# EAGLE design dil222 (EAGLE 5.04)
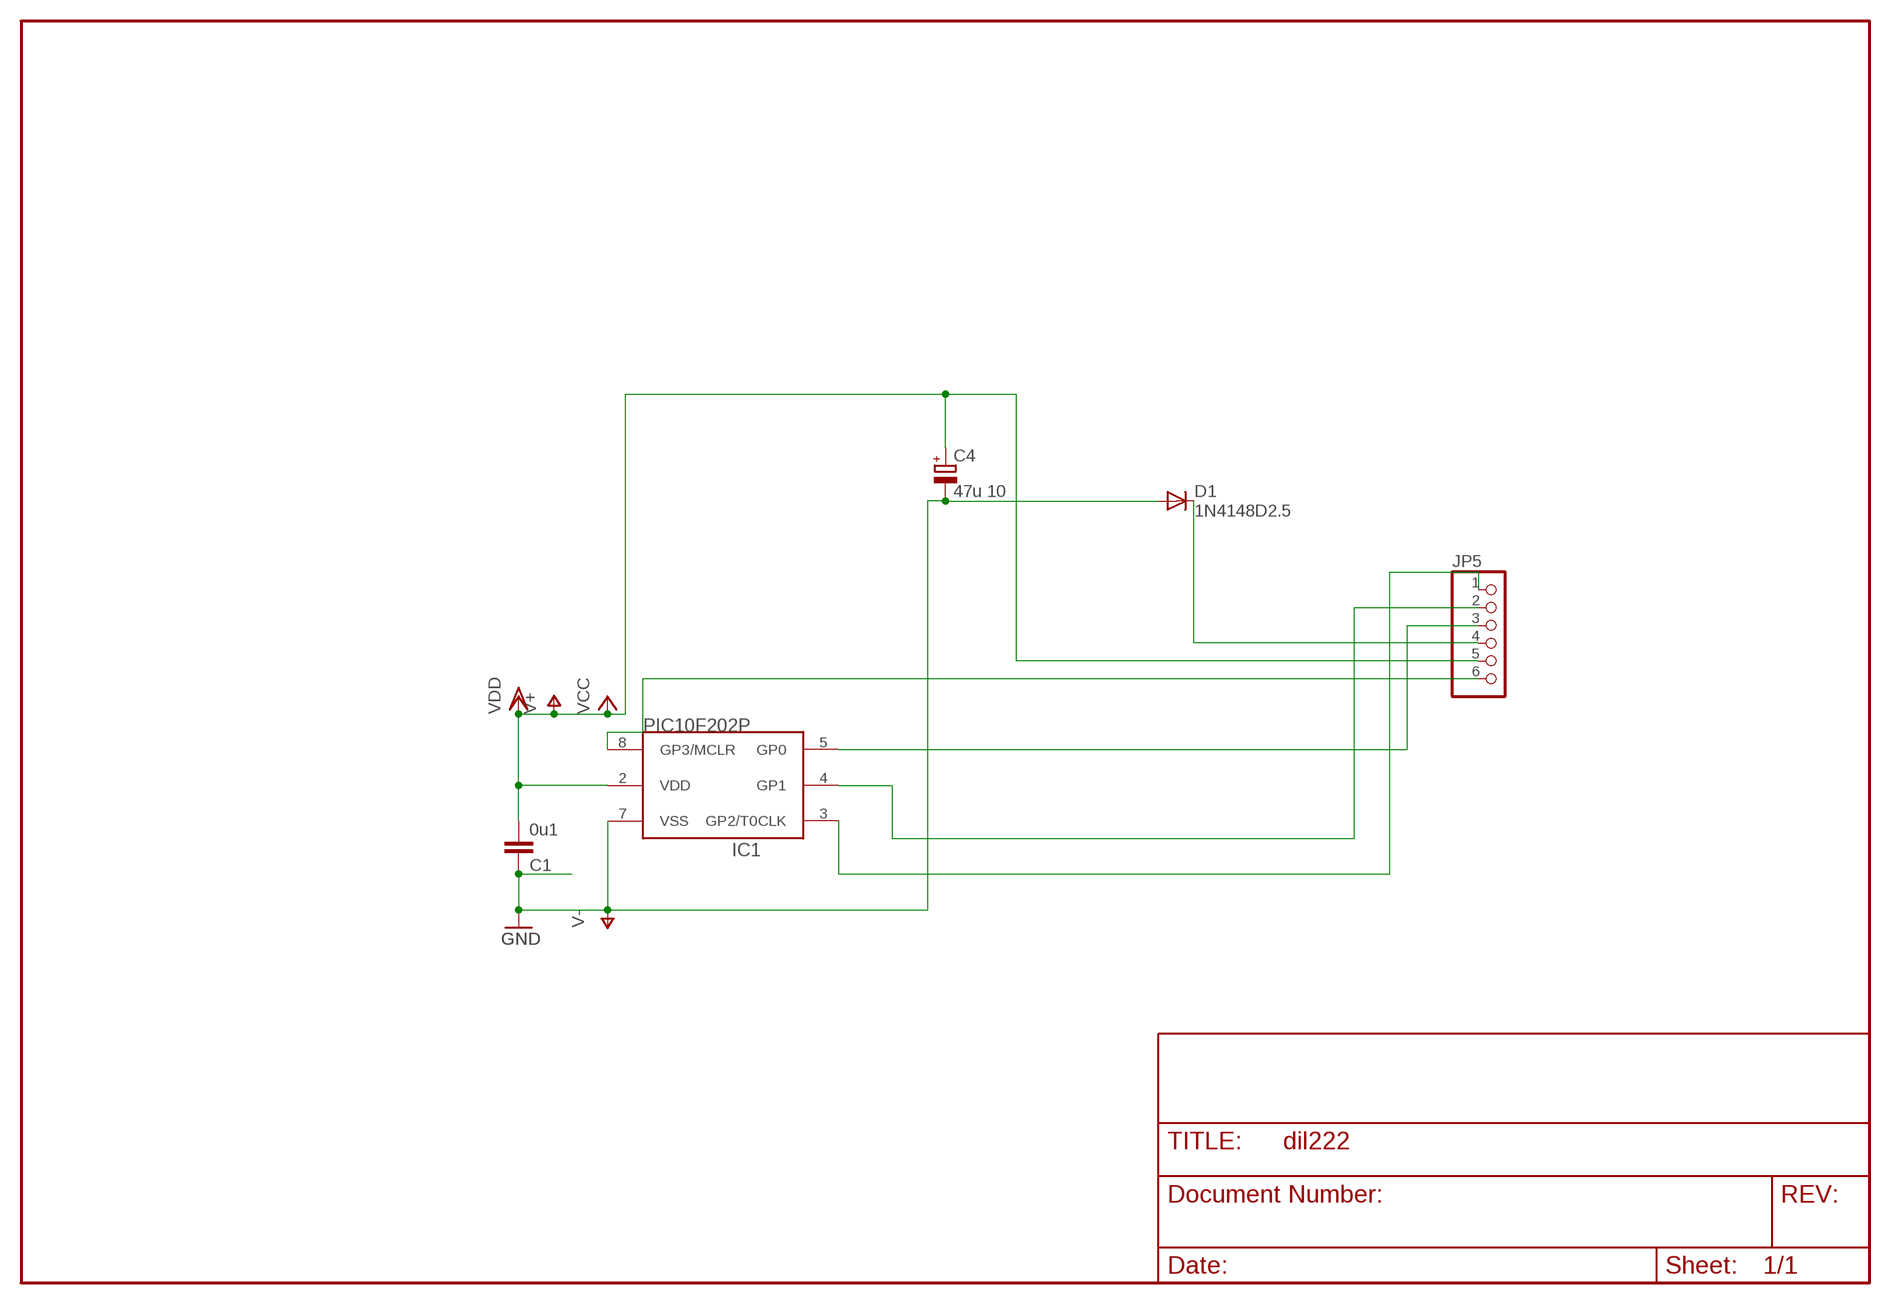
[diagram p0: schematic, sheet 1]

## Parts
C1  0u1  C-EUC1206  [C1206]
C4  47u 10  CPOL-EUE2.5-6  [E2,5-6]
D1  1N4148D2.5  [D-2.5]
IC1  PIC10F202P  [DIL8]
JP5  PINHD-1X6  [1X06]

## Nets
GND: C1.1 C4.- D1.A IC1.7(VSS) ; supply symbol labelled V-
N$2: D1.C JP5.4
N$3: IC1.8(GP3/MCLR) JP5.6
N$4: IC1.4(GP1) JP5.2
N$5: IC1.5(GP0) JP5.3
N$7: IC1.3(GP2/T0CLK) JP5.1
V+: C1.2 C4.+ IC1.2(VDD) JP5.5 ; supply symbol labelled VCC, VDD

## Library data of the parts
C1 = rcl:C-EU: CAPACITOR, European symbol
C4 = rcl:CPOL-EU: POLARIZED CAPACITOR, European symbol
D1 = diode:1N4148: DIODE
IC1 = microchip-5:PIC10F20*: uPC nW 0,25/0,5k Program Flash memory
JP5 = pinhead:PINHD-1X6: PIN HEADER

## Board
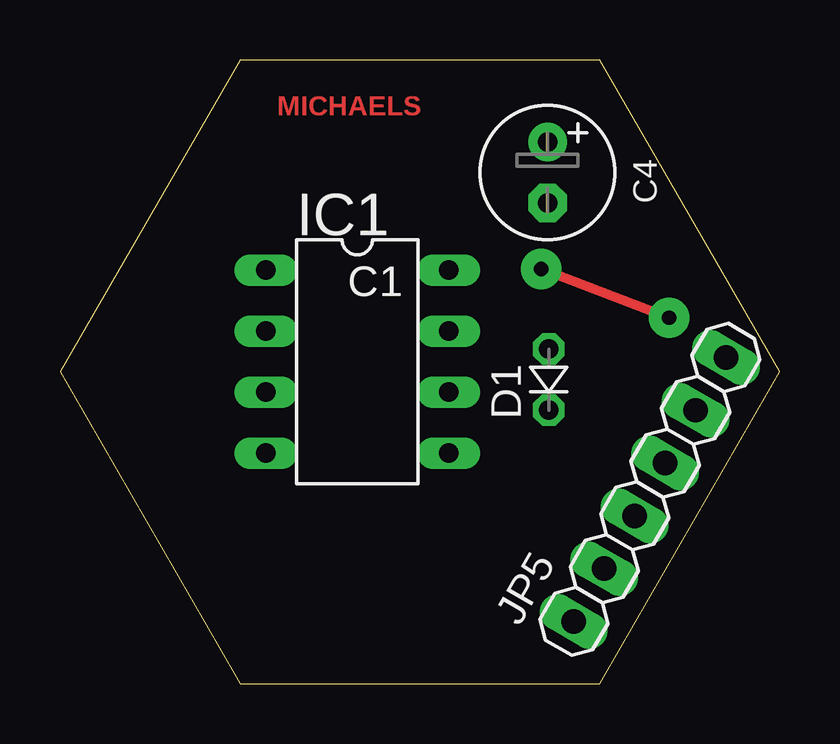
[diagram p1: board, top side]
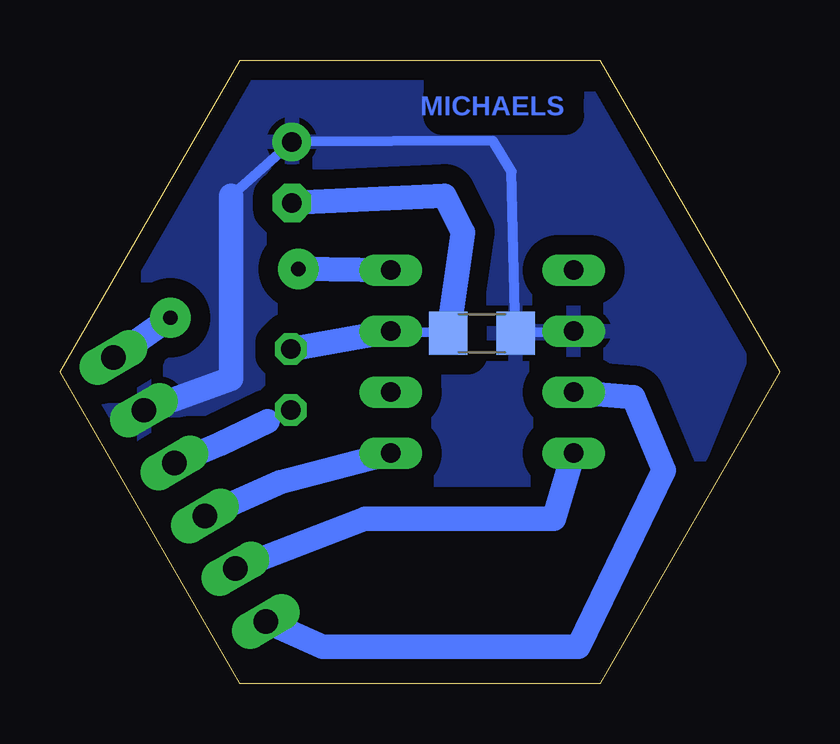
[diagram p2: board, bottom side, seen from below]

Size 30 x 25.98 mm. Coordinates in mm from the lower left corner, seen from the top.
Outline: 7.5,0 22.5,0 30,12.99 22.5,25.98 7.5,25.98 0,12.99 7.5,0
Copper layers (1*16): Top 0.035mm / dielectric 1.5mm / Bottom 0.035mm
Design rules "default *": minimum track width 10mil, minimum drill 24mil, track to track 8mil, track to pad 8mil, pad to pad 8mil, via to via 8mil, smd to smd 8mil, copper to edge 10mil, drill to drill 8mil, minimum pad ring 10mil, minimum via ring 8mil, stop-mask expansion 4mil, vias tented up to drill 0mil, thermal gap 10mil

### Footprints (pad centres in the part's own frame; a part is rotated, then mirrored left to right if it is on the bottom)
C1206 = smd 1.6 x 1.8: 1 -1.4,0; 2 1.4,0
E2,5-6 = drill 0.813 pad 1.6 round: + -1.27,0 | drill 0.813 pad 1.6 octagon: - 1.27,0
D-2.5 = drill 0.813 octagon: A 1.27,0; C -1.27,0
DIL8 = drill 0.813 long: 1 -3.81,-3.81; 2 -1.27,-3.81; 3 1.27,-3.81; 4 3.81,-3.81; 5 3.81,3.81; 6 1.27,3.81; 7 -1.27,3.81; 8 -3.81,3.81
1X06 = drill 1.016 long: 1 -6.35,0; 2 -3.81,0; 3 -1.27,0; 4 1.27,0; 5 3.81,0; 6 6.35,0

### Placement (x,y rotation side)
C1  12.41,14.59 0 bottom
C4  20.33,21.3 270 top
D1  20.38,12.67 90 top
IC1  12.4,13.41 270 top
JP5  24.59,8.08 60 top

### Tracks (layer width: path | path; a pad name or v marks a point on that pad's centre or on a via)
GND
  Bottom 0.406: C1.1 IC1.7
  Bottom 1.016: IC1.7 D1.A | C1.1 13.21,18.8 13.97,20.32 C4.-
N$2
  Bottom 0.406: 23.29,9.98 22.86,10.16 | D1.C 21.34,10.92
  Bottom 1.016: JP5.4 23.29,9.98 21.34,10.92
N$3  (via drill 0.6 pad 1.68)
  Top 0.406: v20.07,17.27 v25.4,15.24
  Bottom 1.016: IC1.8 v20.07,17.27 | v25.4,15.24 JP5.6
N$4
  Bottom 1.016: JP5.2 17.27,6.86 9.4,6.86 IC1.4
N$5
  Bottom 1.016: JP5.3 20.83,8.38 IC1.5
N$7
  Bottom 1.016: JP5.1 19.05,1.52 8.38,1.52 4.83,8.89 6.1,11.94 IC1.3
V+
  Bottom 0.406: 22.86,20.32 C4.+ 11.94,22.61 11.18,21.34 C1.2 IC1.2
  Bottom 1.016: JP5.5 22.86,12.7 22.86,20.32
  pour Bottom (isolate 0.813, rank 6): 5.08,5.08 1.52,13.72 8.38,25.4 22.1,25.4 29.21,13.21 21.59,1.02 7.87,0.76

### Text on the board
Top: MICHAELS
Bottom: MICHAELS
